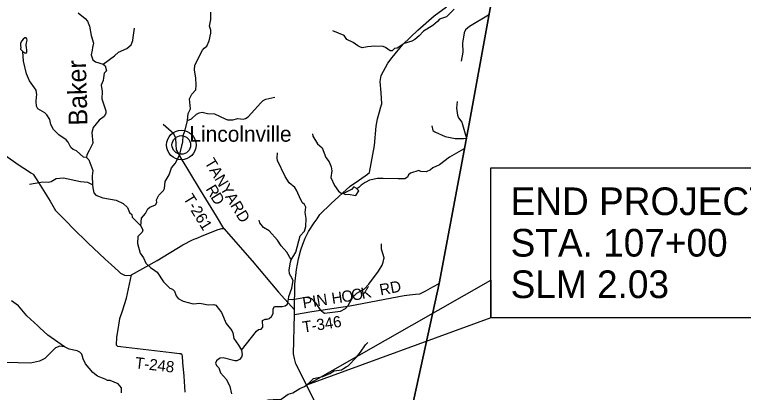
# Model space of a CAD drawing. Extents: x 0 to 34, y 0 to 22.
# Drawn here: x 26.267 to 29.954, y 17.006 to 18.918 of the extents above; entities that cross this region are included whole.
import ezdxf

# ---------------------------------------------------------------- set-up
doc = ezdxf.new("R2010")
doc.units = 0
for name, color, linetype in [('GM_X_Adjacent_County', 7, 'Continuous'), ('GM_X_County', 7, 'Continuous'), ('GM_X_Major_River', 7, 'Continuous'), ('GM_X_Major_River_Text', 7, 'Continuous'), ('GM_X_Minor_Lake', 7, 'Continuous'), ('GM_X_Minor_River', 7, 'Continuous'), ('GM_X_State_Route', 7, 'Continuous'), ('GM_X_Township', 7, 'Continuous'), ('GM_X_Township_Road', 7, 'Continuous'), ('GM_X_Township_Road_Text', 7, 'Continuous'), ('GM_X_Township_ROW', 7, 'Continuous'), ('GM_X_Unincorporated', 7, 'Continuous'), ('GM_X_Unincorporated_Location', 7, 'Continuous'), ('GM_X_Unincorporated_Text', 7, 'Continuous'), ('SH_Data', 7, 'Continuous'), ('SH_Text', 7, 'Continuous')]:
    doc.layers.add(name, color=color, linetype=linetype)

msp = doc.modelspace()

# ---------------------------------------------------------------- linework, layer by layer
at = {"layer": 'GM_X_Adjacent_County'}
msp.add_lwpolyline([(29.025, 20.9), (28.9523, 20.4546), (28.8745, 20.061), (28.5665, 18.3656), (28.4154, 17.5565), (28.2182, 16.6548), (28.1843, 16.461), (28.0039, 15.594), (27.9998, 15.5735), (27.9456, 15.2665), (28.3274, 15.217), (28.5345, 15.206), (29.5448, 15.1357), (29.7209, 15.1252), (30.2392, 15.0941), (30.8167, 15.0595)], dxfattribs=at)
at = {"layer": 'GM_X_County'}
msp.add_lwpolyline([(24.0167, 14.5214), (24.6978, 14.628), (24.8262, 14.6485), (26.4085, 14.9262), (26.4461, 14.9325), (27.6234, 15.1875), (27.9456, 15.2665), (27.9998, 15.5735), (28.0039, 15.594), (28.1843, 16.461), (28.2182, 16.6548), (28.4154, 17.5565), (28.5665, 18.3656), (28.8745, 20.061), (28.9523, 20.4546), (29.025, 20.9)], dxfattribs=at)
at = {"layer": 'GM_X_Major_River'}
for points in [[(26.5889, 18.9266), (26.6246, 18.8971), (26.6362, 18.8841), (26.6465, 18.8586), (26.6547, 18.8119), (26.6661, 18.7735), (26.6609, 18.7508), (26.6586, 18.7383), (26.6549, 18.7141), (26.663, 18.6893), (26.6761, 18.679), (26.7157, 18.6668), (26.7259, 18.658), (26.7313, 18.6326), (26.7209, 18.6205), (26.7162, 18.5982), (26.7157, 18.5849), (26.7045, 18.5597), (26.7094, 18.5278), (26.7087, 18.4914), (26.7293, 18.4301), (26.7291, 18.4165), (26.7203, 18.4026), (26.6955, 18.3831), (26.6641, 18.3466), (26.6578, 18.3213), (26.6622, 18.2667), (26.6444, 18.2305), (26.6332, 18.2078), (26.6312, 18.195), (26.6428, 18.1827), (26.6627, 18.1287), (26.6598, 18.1014), (26.6605, 18.0556), (26.6622, 18.0404), (26.6677, 18.0153), (26.6774, 18.0038), (26.7136, 17.9902), (26.7804, 17.9793), (26.8158, 17.9623), (26.8383, 17.9408), (26.8479, 17.9161), (26.8599, 17.9054), (26.8613, 17.8928), (26.9055, 17.8488)], [(26.9055, 17.8488), (26.9155, 17.8263), (26.9124, 17.8165), (26.8902, 17.794), (26.8891, 17.7584), (26.903, 17.7097), (26.919, 17.6872), (26.9316, 17.6601), (26.9549, 17.6379), (26.9766, 17.6226), (26.9879, 17.6133), (27.02, 17.5645), (27.0529, 17.5335), (27.0654, 17.5288), (27.0766, 17.5177), (27.0836, 17.4937), (27.0937, 17.4811), (27.1196, 17.4676), (27.1698, 17.4531), (27.2043, 17.4577), (27.2462, 17.4485), (27.2742, 17.4509), (27.2844, 17.447), (27.3042, 17.4233), (27.3135, 17.4096), (27.338, 17.3544), (27.3652, 17.3192), (27.3712, 17.3074), (27.3758, 17.279), (27.4004, 17.2442), (27.4149, 17.2187), (27.4189, 17.1959), (27.4154, 17.1842), (27.4039, 17.1714), (27.3913, 17.1662), (27.3807, 17.1656), (27.3226, 17.1813), (27.3075, 17.1784), (27.298, 17.1732), (27.288, 17.1657), (27.2838, 17.1529), (27.2878, 17.1411), (27.3002, 17.1292), (27.3086, 17.1053), (27.3389, 17.0709), (27.3552, 17.0362), (27.3643, 16.9986)]]:
    msp.add_lwpolyline(points, dxfattribs=at)
at = {"layer": 'GM_X_Minor_Lake'}
for points in [[(26.3078, 18.7311), (26.3187, 18.7238), (26.3228, 18.7223), (26.327, 18.7234), (26.3289, 18.729), (26.329, 18.7381), (26.3265, 18.751), (26.3262, 18.7632), (26.3271, 18.7749), (26.3303, 18.7889), (26.3296, 18.7957), (26.3247, 18.8007), (26.3194, 18.7996), (26.3107, 18.794), (26.3034, 18.7846), (26.2972, 18.7726), (26.2967, 18.7597), (26.2977, 18.7513), (26.2965, 18.7422)], [(26.2965, 18.7422), (26.3078, 18.7311)], [(27.9948, 18.04), (27.9823, 18.0459), (27.9705, 18.0331), (27.9313, 18.0122), (27.9415, 18.0065), (27.9547, 18.0094), (27.9936, 18.0014), (28.0086, 18.0255)], [(28.0086, 18.0255), (27.9948, 18.04)]]:
    msp.add_lwpolyline(points, dxfattribs=at)
at = {"layer": 'GM_X_Minor_River'}
for points in [[(26.9055, 17.8488), (26.9093, 17.8871), (26.9299, 17.9103), (26.9404, 17.9341), (26.9514, 17.9427), (26.9796, 17.9542), (26.9857, 17.9663), (26.9851, 17.9796), (26.9971, 18.0045), (27.0208, 18.027), (27.025, 18.0375), (27.0284, 18.0728), (27.0484, 18.1067), (27.0612, 18.1414), (27.0785, 18.164), (27.0981, 18.199), (27.1032, 18.2134), (27.1182, 18.2724), (27.1189, 18.3061), (27.1305, 18.3322), (27.1423, 18.3817), (27.1446, 18.4173), (27.1562, 18.4415), (27.1517, 18.4912), (27.1637, 18.5149), (27.1836, 18.5371), (27.185, 18.5602), (27.1838, 18.5981), (27.1774, 18.6357), (27.178, 18.6611), (27.217, 18.7369), (27.2262, 18.7478), (27.2388, 18.7575), (27.2511, 18.7855), (27.2591, 18.8244), (27.2592, 18.8385), (27.2537, 18.8582), (27.2605, 18.8923), (27.2594, 18.9291)], [(28.4899, 18.9445), (28.4525, 18.9059), (28.416, 18.8949), (28.4057, 18.8821), (28.382, 18.863), (28.3348, 18.8335), (28.3134, 18.8102), (28.2913, 18.7922), (28.2761, 18.7837), (28.2385, 18.7711), (28.2023, 18.7476), (28.1891, 18.7462), (28.1772, 18.735), (28.1674, 18.7347), (28.1426, 18.7516), (28.1316, 18.7555), (28.0897, 18.7578), (28.0522, 18.7544), (28.0249, 18.7498), (28.0132, 18.7537), (28.003, 18.7598), (27.979, 18.7767), (27.9485, 18.7922), (27.9339, 18.8113), (27.877, 18.8354)], [(28.6647, 18.9143), (28.5678, 18.857)], [(26.7157, 18.6668), (26.7725, 18.7083), (26.7931, 18.7271), (26.8349, 18.7452), (26.8559, 18.7644), (26.8652, 18.787), (26.8673, 18.8022), (26.8742, 18.8487)], [(28.5678, 18.857), (28.5479, 18.8397), (28.5406, 18.8261), (28.5325, 18.7724), (28.5343, 18.728), (28.5259, 18.6826)], [(26.6312, 18.195), (26.615, 18.1966), (26.5793, 18.2273), (26.5639, 18.2351), (26.5519, 18.2454), (26.5385, 18.2717), (26.5277, 18.2836), (26.4909, 18.3097), (26.4646, 18.3361), (26.4509, 18.3609), (26.4451, 18.3871), (26.4306, 18.4096), (26.4193, 18.4211), (26.384, 18.4415), (26.3777, 18.4541), (26.3756, 18.4776), (26.3785, 18.5007), (26.3797, 18.5113), (26.3754, 18.5352), (26.3422, 18.583), (26.3267, 18.6176), (26.3118, 18.6822), (26.3078, 18.7311)], [(27.1423, 18.3817), (27.1625, 18.3906), (27.1873, 18.4131), (27.2014, 18.4209), (27.2154, 18.4234), (27.2426, 18.4167), (27.2777, 18.4149), (27.3327, 18.3893), (27.3448, 18.3842), (27.3713, 18.3844), (27.3955, 18.3921), (27.4227, 18.3884), (27.4356, 18.3913), (27.449, 18.3995), (27.5121, 18.4709), (27.5243, 18.4822), (27.5376, 18.4892), (27.5835, 18.499)], [(28.5053, 18.4774), (28.5031, 18.4444), (28.5069, 18.4091), (28.5125, 18.3958), (28.53, 18.3733), (28.5461, 18.3147), (28.551, 18.2993)], [(28.3785, 18.3554), (28.3828, 18.3315), (28.3926, 18.3238), (28.4449, 18.3013), (28.4963, 18.2913), (28.5372, 18.2913), (28.5497, 18.2928)], [(27.7739, 18.3144), (27.776, 18.3019), (27.7999, 18.2637), (27.8235, 18.243), (27.8423, 18.1951), (27.8587, 18.1718), (27.8679, 18.1474), (27.8719, 18.1269), (27.867, 18.094), (27.8855, 18.0521), (27.9064, 18.0242), (27.9188, 18.0135), (27.9317, 18.012)], [(27.4149, 17.2187), (27.49, 17.315), (27.5015, 17.3236), (27.5147, 17.3253), (27.5235, 17.3359), (27.5212, 17.3692), (27.5353, 17.3767), (27.5451, 17.3762), (27.5546, 17.3795), (27.5664, 17.3893), (27.5745, 17.4043), (27.5752, 17.4282), (27.5821, 17.4403), (27.6214, 17.4399), (27.6358, 17.4432), (27.6473, 17.4529), (27.6528, 17.4767), (27.6541, 17.4907), (27.6689, 17.5331), (27.6765, 17.5724), (27.6642, 17.5934), (27.6583, 17.6063), (27.6554, 17.6264), (27.663, 17.6646), (27.6662, 17.6771), (27.69, 17.7155), (27.712, 17.7976), (27.7334, 17.8213), (27.7408, 17.8451), (27.7428, 17.886), (27.7374, 17.9164), (27.7399, 17.9433), (27.7344, 17.9562), (27.7242, 17.9643), (27.716, 17.9768), (27.7005, 18.0142), (27.6923, 18.0286), (27.6845, 18.042), (27.656, 18.0661), (27.6351, 18.0982), (27.5966, 18.1797), (27.5948, 18.1918), (27.597, 18.2187)], [(28.5384, 18.2366), (28.4673, 18.1953), (28.417, 18.1572), (28.3821, 18.142), (28.3702, 18.1322), (28.3489, 18.1214), (28.3229, 18.1236), (28.3127, 18.129), (28.2702, 18.1143), (28.2603, 18.1068), (28.2541, 18.0943), (28.2419, 18.0861), (28.2075, 18.0865), (28.1311, 18.0884), (28.1031, 18.0879), (28.0625, 18.0792), (28.0401, 18.068), (28.0202, 18.0538), (28.0084, 18.0418), (27.9991, 18.0355)], [(26.6605, 18.0556), (26.6368, 18.0672), (26.6009, 18.0705), (26.5144, 18.0892), (26.478, 18.0858), (26.4526, 18.072), (26.4393, 18.0684), (26.409, 18.069), (26.3416, 18.058)], [(27.6662, 17.6771), (27.6434, 17.7145), (27.615, 17.7474), (27.5972, 17.7767), (27.5549, 17.8234), (27.5255, 17.8396), (27.508, 17.8641), (27.5036, 17.8777)], [(27.6528, 17.4767), (27.6751, 17.475), (27.7305, 17.4866), (27.7441, 17.4876), (27.7683, 17.4801), (27.79, 17.4587), (27.8135, 17.424), (27.8352, 17.4059), (27.9159, 17.4173), (27.9407, 17.4299), (27.9537, 17.4457), (27.9776, 17.4875), (27.9982, 17.5086), (28.037, 17.5305), (28.0596, 17.5538), (28.1083, 17.62), (28.1263, 17.6498), (28.1322, 17.6642), (28.1358, 17.6869), (28.1234, 17.7302), (28.1229, 17.7575)], [(26.8071, 17.0041), (26.8081, 17.0287), (26.7909, 17.0494), (26.7502, 17.0653), (26.7362, 17.0658), (26.7245, 17.072), (26.7117, 17.0778), (26.6865, 17.0872), (26.6632, 17.1067), (26.6262, 17.1503), (26.6143, 17.1755), (26.6077, 17.199), (26.5972, 17.2097), (26.5833, 17.2159), (26.5429, 17.2251), (26.5192, 17.2363), (26.435, 17.2955), (26.3953, 17.333), (26.384, 17.3422), (26.3282, 17.3928), (26.2874, 17.4429), (26.2506, 17.4694)], [(27.4042, 16.8981), (27.4173, 16.9173), (27.4611, 16.9502), (27.4887, 16.9519), (27.5517, 16.9675), (27.5755, 16.97), (27.6157, 16.9715), (27.6511, 16.9973), (27.675, 17.0035), (27.71, 17.0255), (27.7332, 17.0351), (27.7561, 17.0527), (27.7786, 17.0763), (27.826, 17.0869), (27.8625, 17.102), (27.8842, 17.1155), (27.9206, 17.1204), (27.9312, 17.1268), (27.9449, 17.135), (27.9544, 17.1406), (27.9972, 17.1845), (28.0172, 17.2085), (28.0421, 17.247), (28.0547, 17.2586)], [(26.5192, 17.2363), (26.4958, 17.2388), (26.4737, 17.2314), (26.4206, 17.1774), (26.3932, 17.1633), (26.3477, 17.1538), (26.2218, 17.157), (26.1593, 17.1462), (26.1017, 17.1389), (26.0249, 17.1392)]]:
    msp.add_lwpolyline(points, dxfattribs=at)
at = {"layer": 'GM_X_State_Route'}
for points in [[(27.6833, 17.4233), (27.6844, 17.5531), (27.6929, 17.6278), (27.7033, 17.682), (27.7152, 17.7267), (27.7247, 17.7566), (27.7368, 17.7857), (27.7542, 17.8204), (27.7824, 17.8637), (27.7974, 17.8837), (27.811, 17.9067), (27.8677, 17.9618), (27.9654, 18.0495), (28.0062, 18.0778), (28.0406, 18.1013), (28.0528, 18.1095), (28.0628, 18.1182), (28.0872, 18.2557), (28.0966, 18.3524), (28.1028, 18.3907), (28.1123, 18.4252), (28.1205, 18.4501), (28.1249, 18.4668), (28.1214, 18.5219), (28.1171, 18.5797), (28.122, 18.6088), (28.1557, 18.6711), (28.1773, 18.7012), (28.2307, 18.7655), (28.3077, 18.8394), (28.3901, 18.9121), (28.4512, 18.9569)], [(25.4106, 18.7356), (25.4107, 18.7355), (25.4169, 18.7263), (25.4529, 18.6959), (25.5517, 18.6241), (25.595, 18.5962), (25.6047, 18.5877), (25.7711, 18.4934), (25.8707, 18.4254), (26.0163, 18.3329), (26.0814, 18.2937), (26.2164, 18.2082), (26.2893, 18.1564), (26.3375, 18.1258), (26.3484, 18.117), (26.3608, 18.1096), (26.3798, 18.082), (26.4467, 17.9726), (26.4746, 17.9255), (26.5304, 17.8687), (26.5618, 17.8376), (26.5618, 17.8375)], [(26.5618, 17.8375), (26.6368, 17.7633), (26.7252, 17.6795), (26.7556, 17.6529), (26.7942, 17.6167), (26.8025, 17.6083), (26.8232, 17.5997), (26.8349, 17.5965), (26.8562, 17.5989), (26.8585, 17.6002), (26.9881, 17.6725), (27.1183, 17.7529), (27.1671, 17.7774), (27.1843, 17.7846)], [(27.1843, 17.7846), (27.1847, 17.7847), (27.2235, 17.801), (27.2969, 17.8305), (27.3152, 17.8344), (27.3247, 17.8343), (27.4694, 17.6712), (27.6028, 17.5123), (27.6833, 17.4233)], [(27.8092, 16.912), (27.6895, 17.1494), (27.6823, 17.178), (27.678, 17.2008), (27.6827, 17.3991), (27.6833, 17.4233)], [(27.7835, 16.9629), (27.7432, 17.0428)]]:
    msp.add_lwpolyline(points, dxfattribs=at)
at = {"layer": 'GM_X_Township'}
msp.add_lwpolyline([(24.0167, 14.5214), (24.6978, 14.628), (24.8262, 14.6485), (26.4085, 14.9262), (26.4461, 14.9325), (27.6234, 15.1875), (27.9456, 15.2665), (27.9998, 15.5735), (28.0039, 15.594), (28.1843, 16.461), (28.2182, 16.6548), (28.4154, 17.5565), (28.5665, 18.3656), (28.8745, 20.061), (28.9523, 20.4546), (29.025, 20.9)], dxfattribs=at)
at = {"layer": 'GM_X_Township_Road'}
for points in [[(27.1054, 18.2002), (27.1053, 18.2004), (27.0853, 18.2338), (27.0836, 18.2603), (27.0819, 18.2922), (27.0723, 18.3146), (27.0183, 18.362)], [(27.3247, 17.8343), (27.2892, 17.8979), (27.208, 18.0288), (27.1054, 18.2002)], [(26.7927, 17.3344), (26.7927, 17.3345), (26.7996, 17.3795), (26.8126, 17.4186), (26.8323, 17.4825), (26.8585, 17.6002)], [(27.6827, 17.3991), (27.7705, 17.415), (27.963, 17.4435), (28.2383, 17.4956), (28.2652, 17.4992), (28.2952, 17.5028), (28.3175, 17.5044), (28.3466, 17.5202), (28.3833, 17.5405), (28.4154, 17.5565)], [(27.102, 17.2016), (27.1017, 17.2016), (27.0612, 17.2053), (26.8032, 17.2356), (26.7888, 17.2378), (26.7819, 17.2454), (26.785, 17.2849), (26.7927, 17.3344)]]:
    msp.add_lwpolyline(points, dxfattribs=at)
at = {"layer": 'GM_X_Township_ROW'}
msp.add_lwpolyline([(27.1291, 17.0076), (27.1253, 17.088), (27.1173, 17.1571), (27.1163, 17.1889), (27.1151, 17.1958), (27.1079, 17.201), (27.102, 17.2016)], dxfattribs=at)
at = {"layer": 'GM_X_Unincorporated'}
for radius in [0.0744, 0.0472]:
    msp.add_circle((27.1104, 18.2577), radius, dxfattribs=at)
at = {"layer": 'GM_X_Unincorporated_Location'}
msp.add_line((27.1104, 18.2577), (27.1104, 18.2577), dxfattribs=at)
at = {"layer": 'SH_Data'}
for points in [[(28.6763, 18.1429), (30.3199, 18.1429), (30.3199, 17.3829), (28.6763, 17.3829)], [(28.6763, 17.3829), (27.7432, 17.0428), (28.6763, 17.5729)]]:
    msp.add_lwpolyline(points, close=True, dxfattribs=at)

# ---------------------------------------------------------------- texts
at = {"layer": 'GM_X_Major_River_Text'}
msp.add_text('Baker', height=0.09471, rotation=91.4455, dxfattribs=at).set_placement((26.636, 18.3571))
at = {"layer": 'GM_X_Township_Road_Text'}
for s, height, rotation, p in [('TANYARD', 0.05682, 300.963, (27.2261, 18.1697)), ('R', 0.0568, 300.7824, (27.2318, 18.0351)), ('T-261', 0.05682, 301.4812, (27.1182, 17.9885)), ('D', 0.0568, 302.145, (27.2564, 17.9938)), ('RD', 0.05682, 10.9226, (28.1189, 17.4961)), ('H', 0.0568, 8.4232, (27.8749, 17.4529)), ('O', 0.0568, 9.3261, (27.9254, 17.4604)), ('O', 0.0568, 10.5559, (27.976, 17.4687)), ('K', 0.0568, 10.8076, (28.0254, 17.478)), ('PIN', 0.05682, 8.9744, (27.7283, 17.4303)), ('T-346', 0.05682, 8.8284, (27.7278, 17.3077)), ('T-248', 0.05682, 353.2248, (26.874, 17.1287))]:
    msp.add_text(s, height=height, rotation=rotation, dxfattribs=at).set_placement(p)
at = {"layer": 'GM_X_Unincorporated_Text'}
msp.add_text('Lincolnville', height=0.078977, rotation=0, dxfattribs=at).set_placement((27.1515, 18.2741))
at = {"layer": 'SH_Text'}
for s, p in [('END PROJECT ', (28.7763, 17.9029)), ('STA. 107+00', (28.7763, 17.6929)), ('SLM 2.03', (28.7763, 17.4829))]:
    msp.add_text(s, height=0.14, dxfattribs=at).set_placement(p)

doc.saveas('drawing.dxf')
